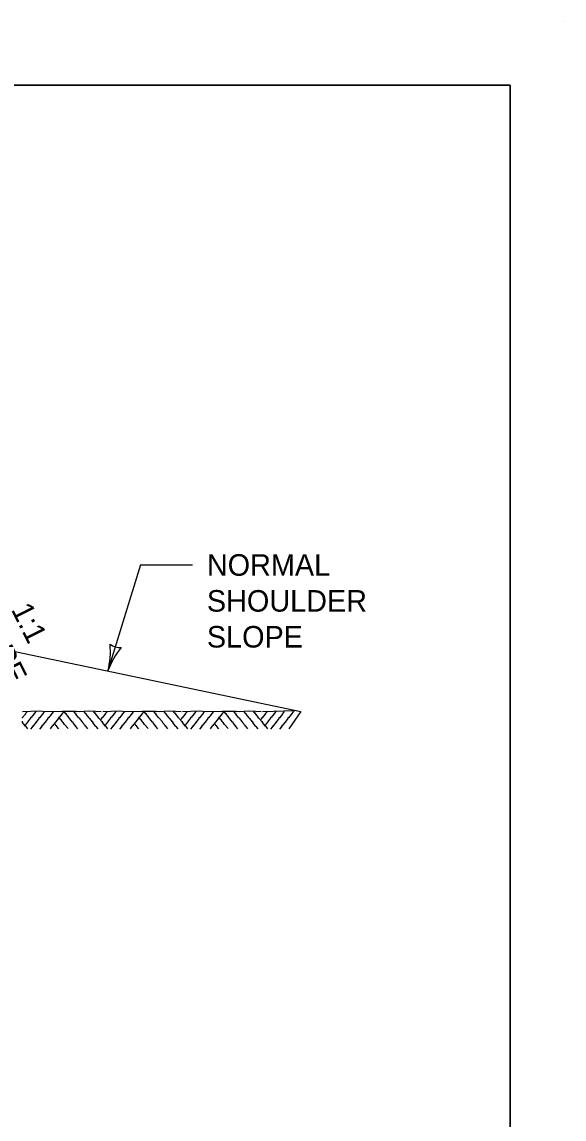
# Model space of a CAD drawing. Extents: x 49991.4 to 50021, y 49987.6 to 50011.4.
# Drawn here: x 50015.391 to 50016.9, y 49996.12 to 49999.176 of the extents above; entities that cross this region are included whole.
import ezdxf

# ---------------------------------------------------------------- set-up
doc = ezdxf.new("R2010")
doc.units = 0
for name, color, linetype in [('Level 1', 7, 'Continuous'), ('Level 2', 7, 'Continuous'), ('Level 3', 7, 'Continuous'), ('Level 4', 7, 'Continuous')]:
    doc.layers.add(name, color=color, linetype=linetype)

msp = doc.modelspace()

# ---------------------------------------------------------------- linework, layer by layer
at = {"layer": 'Level 1'}
for p, q in [((50016.9001, 49999.1756), (50016.9001, 49999.1756)), ((50016.1675, 49997.2547), (50016.1336, 49997.2064))]:
    msp.add_line(p, q, dxfattribs=at)
msp.add_lwpolyline([(49999.3835, 49998.9992), (50016.7501, 49998.9992), (50016.7501, 49987.7988), (49999.3835, 49987.7988)], close=True, dxfattribs=at)
for points in [[(50015.4059, 49997.255), (50015.3999, 49997.2479), (50015.4006, 49997.2464), (50015.3992, 49997.2464), (50015.3916, 49997.237), (50015.3908, 49997.237)], [(50015.3926, 49997.2545), (50015.4398, 49997.2564), (50015.4576, 49997.2545), (50015.5032, 49997.256), (50015.5416, 49997.2562), (50015.5523, 49997.2548), (50015.5772, 49997.2564), (50015.5964, 49997.2554), (50015.6112, 49997.2545)], [(50015.4305, 49997.2562), (50015.4245, 49997.249), (50015.4252, 49997.2474), (50015.4238, 49997.2474), (50015.4164, 49997.238), (50015.4143, 49997.238), (50015.4148, 49997.2364), (50015.4071, 49997.2268), (50015.4071, 49997.2248), (50015.4053, 49997.2244), (50015.3993, 49997.2164)], [(50015.453, 49997.2544), (50015.4476, 49997.2478), (50015.448, 49997.2462), (50015.4467, 49997.2462), (50015.4392, 49997.2368), (50015.4374, 49997.2368), (50015.4376, 49997.235), (50015.4299, 49997.2254), (50015.4299, 49997.2234), (50015.4284, 49997.223), (50015.421, 49997.2134), (50015.4192, 49997.2134), (50015.4196, 49997.2114), (50015.4143, 49997.2052)], [(50015.4786, 49997.2552), (50015.4726, 49997.2479), (50015.4734, 49997.2464), (50015.4719, 49997.2464), (50015.4644, 49997.237), (50015.4626, 49997.237), (50015.4629, 49997.2352), (50015.4551, 49997.2256), (50015.4551, 49997.2239), (50015.4536, 49997.2232), (50015.4462, 49997.2138), (50015.4443, 49997.2136), (50015.4448, 49997.2119), (50015.4395, 49997.2053)], [(50015.508, 49997.256), (50015.502, 49997.2488), (50015.5028, 49997.2473), (50015.5016, 49997.2473), (50015.4941, 49997.238), (50015.4922, 49997.238), (50015.4923, 49997.236), (50015.4846, 49997.2264), (50015.4846, 49997.2248), (50015.483, 49997.224), (50015.4756, 49997.2148), (50015.474, 49997.2144), (50015.4743, 49997.2128), (50015.469, 49997.2064)], [(50015.5466, 49997.2064), (50015.5418, 49997.2126), (50015.5402, 49997.2124), (50015.5406, 49997.2138), (50015.5331, 49997.223), (50015.5334, 49997.225), (50015.5316, 49997.225), (50015.5241, 49997.2348), (50015.5223, 49997.2352), (50015.522, 49997.2368), (50015.5145, 49997.2462), (50015.5148, 49997.2479), (50015.513, 49997.248), (50015.5079, 49997.2546)], [(50015.5738, 49997.2068), (50015.5682, 49997.2142), (50015.5666, 49997.2138), (50015.567, 49997.2154), (50015.5595, 49997.2246), (50015.5598, 49997.2264), (50015.5582, 49997.2268), (50015.5505, 49997.2364), (50015.5487, 49997.2366), (50015.5486, 49997.2384), (50015.5409, 49997.2478), (50015.5412, 49997.2496), (50015.5394, 49997.2496), (50015.5343, 49997.2562)], [(50015.6026, 49997.2064), (50015.597, 49997.2134), (50015.5955, 49997.2132), (50015.5958, 49997.2144), (50015.5883, 49997.2239), (50015.5888, 49997.2258), (50015.5868, 49997.226), (50015.5793, 49997.2354), (50015.5775, 49997.2359), (50015.5772, 49997.2378), (50015.5697, 49997.247), (50015.5702, 49997.2488), (50015.5682, 49997.2488), (50015.5632, 49997.2554)], [(50015.613, 49997.2268), (50015.606, 49997.2358), (50015.6042, 49997.236), (50015.604, 49997.2378), (50015.5964, 49997.2472), (50015.5967, 49997.249), (50015.5949, 49997.249), (50015.5895, 49997.2558)], [(50015.6286, 49997.255), (50015.6226, 49997.2479), (50015.6234, 49997.2464), (50015.6219, 49997.2464), (50015.6144, 49997.237), (50015.6135, 49997.237)], [(50015.6156, 49997.2545), (50015.6626, 49997.2564), (50015.6804, 49997.2545), (50015.726, 49997.256), (50015.7644, 49997.2562), (50015.775, 49997.2548), (50015.8001, 49997.2564), (50015.8193, 49997.2554), (50015.834, 49997.2545)], [(50015.6532, 49997.2562), (50015.6472, 49997.249), (50015.648, 49997.2474), (50015.6465, 49997.2474), (50015.6392, 49997.238), (50015.637, 49997.238), (50015.6375, 49997.2364), (50015.6297, 49997.2268), (50015.6297, 49997.2248), (50015.628, 49997.2244), (50015.622, 49997.2164)], [(50015.6758, 49997.2544), (50015.6702, 49997.2478), (50015.6708, 49997.2462), (50015.6696, 49997.2462), (50015.6621, 49997.2368), (50015.6602, 49997.2368), (50015.6603, 49997.235), (50015.6526, 49997.2254), (50015.6526, 49997.2234), (50015.6512, 49997.223), (50015.6438, 49997.2134), (50015.642, 49997.2134), (50015.6423, 49997.2114), (50015.637, 49997.2052)], [(50015.7014, 49997.2552), (50015.6954, 49997.2479), (50015.6962, 49997.2464), (50015.6946, 49997.2464), (50015.6873, 49997.237), (50015.6852, 49997.237), (50015.6856, 49997.2352), (50015.678, 49997.2256), (50015.678, 49997.2239), (50015.6762, 49997.2232), (50015.669, 49997.2138), (50015.667, 49997.2136), (50015.6675, 49997.2119), (50015.6622, 49997.2053)], [(50015.7308, 49997.256), (50015.7248, 49997.2488), (50015.7256, 49997.2473), (50015.7242, 49997.2473), (50015.7167, 49997.238), (50015.7149, 49997.238), (50015.715, 49997.236), (50015.7074, 49997.2264), (50015.7074, 49997.2248), (50015.7058, 49997.224), (50015.6984, 49997.2148), (50015.6968, 49997.2144), (50015.697, 49997.2128), (50015.6918, 49997.2064)], [(50015.7692, 49997.2064), (50015.7644, 49997.2126), (50015.7629, 49997.2124), (50015.7632, 49997.2138), (50015.7556, 49997.223), (50015.7562, 49997.225), (50015.7542, 49997.225), (50015.7467, 49997.2348), (50015.745, 49997.2352), (50015.7448, 49997.2368), (50015.7372, 49997.2462), (50015.7376, 49997.2479), (50015.7358, 49997.248), (50015.7306, 49997.2546)], [(50015.7966, 49997.2068), (50015.7911, 49997.2142), (50015.7893, 49997.2138), (50015.7898, 49997.2154), (50015.7822, 49997.2246), (50015.7826, 49997.2264), (50015.7809, 49997.2268), (50015.7732, 49997.2364), (50015.7716, 49997.2366), (50015.7713, 49997.2384), (50015.7638, 49997.2478), (50015.7641, 49997.2496), (50015.7622, 49997.2496), (50015.757, 49997.2562)], [(50015.8253, 49997.2064), (50015.8198, 49997.2134), (50015.8182, 49997.2132), (50015.8186, 49997.2144), (50015.811, 49997.2239), (50015.8115, 49997.2258), (50015.8096, 49997.226), (50015.802, 49997.2354), (50015.8004, 49997.2359), (50015.8001, 49997.2378), (50015.7926, 49997.247), (50015.7929, 49997.2488), (50015.7911, 49997.2488), (50015.786, 49997.2554)], [(50015.8358, 49997.2268), (50015.8288, 49997.2358), (50015.8271, 49997.236), (50015.8268, 49997.2378), (50015.8192, 49997.2472), (50015.8196, 49997.249), (50015.8176, 49997.249), (50015.8122, 49997.2558)], [(50015.8514, 49997.255), (50015.8454, 49997.2479), (50015.8462, 49997.2464), (50015.8446, 49997.2464), (50015.8372, 49997.237), (50015.8362, 49997.237)], [(50015.838, 49997.2545), (50015.8853, 49997.2564), (50015.9032, 49997.2545), (50015.9488, 49997.256), (50015.9872, 49997.2562), (50015.9978, 49997.2548), (50016.0227, 49997.2564), (50016.042, 49997.2554), (50016.0568, 49997.2545)], [(50015.876, 49997.2562), (50015.87, 49997.249), (50015.8708, 49997.2474), (50015.8692, 49997.2474), (50015.8619, 49997.238), (50015.8598, 49997.238), (50015.8602, 49997.2364), (50015.8526, 49997.2268), (50015.8526, 49997.2248), (50015.8508, 49997.2244), (50015.8448, 49997.2164)], [(50015.8985, 49997.2544), (50015.8931, 49997.2478), (50015.8937, 49997.2462), (50015.8922, 49997.2462), (50015.8847, 49997.2368), (50015.8829, 49997.2368), (50015.883, 49997.235), (50015.8754, 49997.2254), (50015.8754, 49997.2234), (50015.8739, 49997.223), (50015.8664, 49997.2134), (50015.8648, 49997.2134), (50015.865, 49997.2114), (50015.8598, 49997.2052)], [(50015.9242, 49997.2552), (50015.9182, 49997.2479), (50015.9189, 49997.2464), (50015.9174, 49997.2464), (50015.91, 49997.237), (50015.9081, 49997.237), (50015.9084, 49997.2352), (50015.9008, 49997.2256), (50015.9008, 49997.2239), (50015.8991, 49997.2232), (50015.8918, 49997.2138), (50015.8898, 49997.2136), (50015.8902, 49997.2119), (50015.885, 49997.2053)], [(50015.9536, 49997.256), (50015.9477, 49997.2488), (50015.9483, 49997.2473), (50015.9471, 49997.2473), (50015.9396, 49997.238), (50015.9376, 49997.238), (50015.9378, 49997.236), (50015.9302, 49997.2264), (50015.9302, 49997.2248), (50015.9285, 49997.224), (50015.9212, 49997.2148), (50015.9195, 49997.2144), (50015.9198, 49997.2128), (50015.9146, 49997.2064)], [(50015.9921, 49997.2064), (50015.9872, 49997.2126), (50015.9856, 49997.2124), (50015.9861, 49997.2138), (50015.9786, 49997.223), (50015.9789, 49997.225), (50015.9771, 49997.225), (50015.9696, 49997.2348), (50015.9676, 49997.2352), (50015.9675, 49997.2368), (50015.96, 49997.2462), (50015.9602, 49997.2479), (50015.9585, 49997.248), (50015.9534, 49997.2546)], [(50016.0194, 49997.2068), (50016.0137, 49997.2142), (50016.012, 49997.2138), (50016.0125, 49997.2154), (50016.005, 49997.2246), (50016.0053, 49997.2264), (50016.0036, 49997.2268), (50015.996, 49997.2364), (50015.9942, 49997.2366), (50015.994, 49997.2384), (50015.9864, 49997.2478), (50015.9867, 49997.2496), (50015.9849, 49997.2496), (50015.9798, 49997.2562)], [(50016.048, 49997.2064), (50016.0425, 49997.2134), (50016.041, 49997.2132), (50016.0413, 49997.2144), (50016.0338, 49997.2239), (50016.0342, 49997.2258), (50016.0326, 49997.226), (50016.0248, 49997.2354), (50016.0232, 49997.2359), (50016.0227, 49997.2378), (50016.0152, 49997.247), (50016.0156, 49997.2488), (50016.0137, 49997.2488), (50016.0088, 49997.2554)], [(50016.0586, 49997.2268), (50016.0515, 49997.2358), (50016.0497, 49997.236), (50016.0496, 49997.2378), (50016.0419, 49997.2472), (50016.0422, 49997.249), (50016.0404, 49997.249), (50016.0352, 49997.2558)], [(50016.0742, 49997.255), (50016.0682, 49997.2479), (50016.0689, 49997.2464), (50016.0674, 49997.2464), (50016.0599, 49997.237), (50016.059, 49997.237)], [(50016.0608, 49997.2545), (50016.1512, 49997.2581)], [(50016.0988, 49997.2562), (50016.0928, 49997.249), (50016.0935, 49997.2474), (50016.092, 49997.2474), (50016.0846, 49997.238), (50016.0826, 49997.238), (50016.083, 49997.2364), (50016.0752, 49997.2268), (50016.0752, 49997.2248), (50016.0736, 49997.2244), (50016.0676, 49997.2164)], [(50016.1212, 49997.2544), (50016.1157, 49997.2478), (50016.1166, 49997.2462), (50016.1151, 49997.2462), (50016.1076, 49997.2368), (50016.1056, 49997.2368), (50016.1058, 49997.235), (50016.0982, 49997.2254), (50016.0982, 49997.2234), (50016.0966, 49997.223), (50016.0893, 49997.2134), (50016.0875, 49997.2134), (50016.0878, 49997.2114), (50016.0826, 49997.2052)], [(50016.1469, 49997.2552), (50016.1409, 49997.2479), (50016.1416, 49997.2464), (50016.1402, 49997.2464), (50016.1326, 49997.237), (50016.1307, 49997.237), (50016.1312, 49997.2352), (50016.1235, 49997.2256), (50016.1235, 49997.2239), (50016.1217, 49997.2232), (50016.1145, 49997.2138), (50016.1126, 49997.2136), (50016.113, 49997.2119), (50016.1078, 49997.2053)], [(50015.4068, 49997.2065), (50015.4014, 49997.2136), (50015.3998, 49997.2132), (50015.4, 49997.2148), (50015.3926, 49997.224), (50015.393, 49997.226), (50015.3912, 49997.2262), (50015.3908, 49997.2268)], [(50015.4932, 49997.2066), (50015.4881, 49997.2134), (50015.4882, 49997.215), (50015.4863, 49997.2154), (50015.4812, 49997.2218)], [(50015.519, 49997.2072), (50015.5103, 49997.218), (50015.5086, 49997.2185), (50015.5085, 49997.2203), (50015.501, 49997.2294), (50015.5012, 49997.2314), (50015.4992, 49997.2314), (50015.4944, 49997.2378)], [(50015.6132, 49997.237), (50015.6123, 49997.237), (50015.6126, 49997.2352), (50015.6098, 49997.2316)], [(50015.6296, 49997.2065), (50015.6242, 49997.2136), (50015.6225, 49997.2132), (50015.6228, 49997.2148), (50015.6153, 49997.224), (50015.6158, 49997.226), (50015.6141, 49997.2262), (50015.6135, 49997.2268)], [(50015.7162, 49997.2066), (50015.7107, 49997.2134), (50015.711, 49997.215), (50015.709, 49997.2154), (50015.7041, 49997.2218)], [(50015.7418, 49997.2072), (50015.733, 49997.218), (50015.7314, 49997.2185), (50015.7312, 49997.2203), (50015.7238, 49997.2294), (50015.7239, 49997.2314), (50015.7221, 49997.2314), (50015.717, 49997.2378)], [(50015.8361, 49997.237), (50015.835, 49997.237), (50015.8355, 49997.2352), (50015.8325, 49997.2316)], [(50015.8523, 49997.2065), (50015.8469, 49997.2136), (50015.8454, 49997.2132), (50015.8456, 49997.2148), (50015.838, 49997.224), (50015.8385, 49997.226), (50015.8367, 49997.2262), (50015.8362, 49997.2268)], [(50015.9387, 49997.2066), (50015.9336, 49997.2134), (50015.9338, 49997.215), (50015.9318, 49997.2154), (50015.9267, 49997.2218)], [(50015.9645, 49997.2072), (50015.9558, 49997.218), (50015.9542, 49997.2185), (50015.954, 49997.2203), (50015.9465, 49997.2294), (50015.9466, 49997.2314), (50015.9447, 49997.2314), (50015.9399, 49997.2378)], [(50016.0587, 49997.237), (50016.0578, 49997.237), (50016.0582, 49997.2352), (50016.0552, 49997.2316)], [(50016.075, 49997.2065), (50016.0696, 49997.2136), (50016.0682, 49997.2132), (50016.0683, 49997.2148), (50016.0608, 49997.224), (50016.0612, 49997.226), (50016.0596, 49997.2262), (50016.059, 49997.2268)]]:
    msp.add_lwpolyline(points, dxfattribs=at)
at = {"layer": 'Level 2'}
for p, q in [((50016.7501, 49998.9992), (49999.3835, 49998.9992)), ((50016.7501, 49987.7988), (50016.7501, 49998.9992))]:
    msp.add_line(p, q, dxfattribs=at)
at = {"layer": 'Level 3'}
for q in [(50015.6302, 49997.3677), (50015.8656, 49997.663)]:
    msp.add_line((50015.7208, 49997.663), q, dxfattribs=at)
for centre, radius, start, end in [((50015.4133, 49997.4227), 0.2237, 345.7744, 5.0243), ((50015.8315, 49997.2968), 0.2134, 140.4031, 160.5866), ((50015.6663, 49997.4854), 0.0526, 235.0859, 270.8083)]:
    msp.add_arc(centre, radius, start, end, dxfattribs=at)
at = {"layer": 'Level 4'}
msp.add_line((50014.8017, 49997.542), (50016.1675, 49997.2547), dxfattribs=at)

# ---------------------------------------------------------------- texts
at = {"layer": 'Level 2'}
for s, p in [('NORMAL', (50015.9056, 49997.633)), ('SHOULDER', (50015.9056, 49997.533)), ('SLOPE', (50015.9056, 49997.433))]:
    msp.add_text(s, height=0.06, dxfattribs=at).set_placement(p)
for s, p in [('SLOPE', (50015.2347, 49997.5654)), ('1:1', (50015.3595, 49997.5391))]:
    msp.add_text(s, height=0.06, rotation=296.4886, dxfattribs=at).set_placement(p)

doc.saveas('drawing.dxf')
